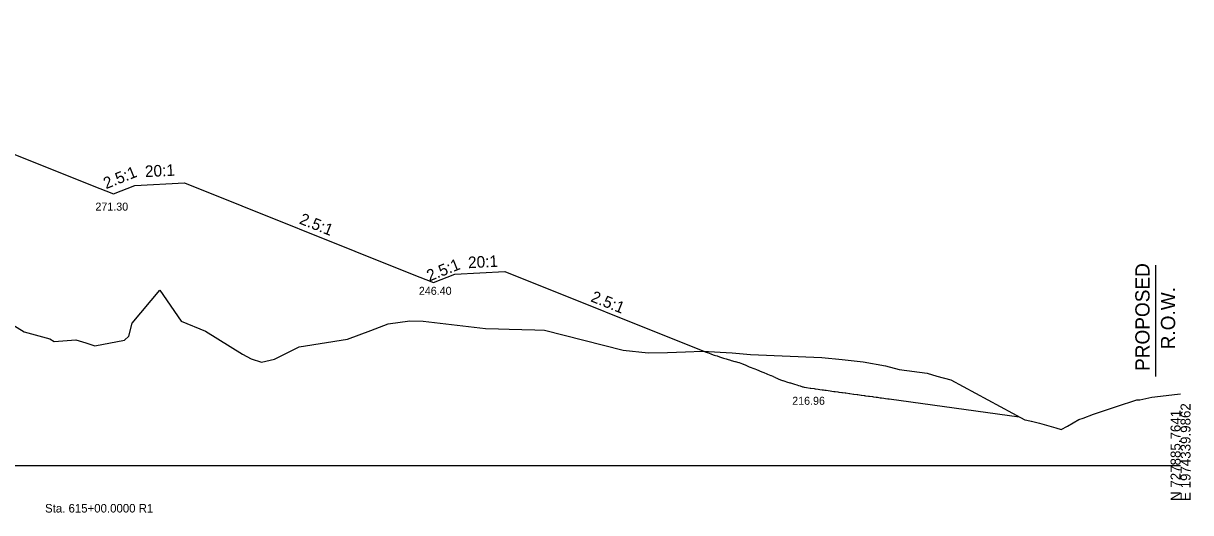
# Model space of a CAD drawing. Extents: x -26 to 1604, y -13 to 9623.
# Drawn here: x 274.6 to 602.8, y 7486.7 to 7624.3 of the extents above; entities that cross this region are included whole.
import ezdxf

# ---------------------------------------------------------------- set-up
doc = ezdxf.new("R2010")
doc.units = 0
for name, color, linetype in [('Default', 7, 'Continuous'), ('Draft_XS_Text', 7, 'Continuous'), ('DTM CONTOURS_MAJOR', 7, 'Continuous'), ('DTM_X_GROUND', 7, 'Continuous'), ('SLOPE_STAKES_FILL', 7, 'Continuous'), ('XS_CELL', 7, 'Continuous'), ('XS_P_GROUND', 7, 'Continuous'), ('XS_P_ROW', 7, 'Continuous'), ('XS_P_TX_DCH', 7, 'Continuous'), ('XS_P_TX_FS_BS', 7, 'Continuous')]:
    doc.layers.add(name, color=color, linetype=linetype)

msp = doc.modelspace()

# ---------------------------------------------------------------- linework, layer by layer
at = {"layer": 'DTM_X_GROUND'}
msp.add_lwpolyline([(269.72, 7540.77), (274.89, 7537.54), (282.09, 7535.56), (283.29, 7534.81), (289.43, 7535.33), (292.18, 7534.46), (294.73, 7533.65), (303.1, 7535.17), (304.3, 7536.31), (305.2, 7539.95), (313.03, 7549.27), (319.02, 7540.54), (325.89, 7537.71), (336.27, 7531.28), (338.67, 7529.99), (341.63, 7528.98), (345.22, 7529.84), (352.21, 7533.32), (365.74, 7535.45), (372.32, 7537.95), (377.24, 7539.82), (383.32, 7540.6), (387.02, 7540.5), (404.55, 7538.51), (408.22, 7538.4), (411.21, 7538.31), (414.82, 7538.19), (418.44, 7538.07), (421.16, 7537.97), (443.29, 7532.39), (450.3, 7531.61), (455.71, 7531.78), (460.79, 7531.93), (465.59, 7532.08), (473.92, 7531.67), (479.05, 7531.13), (499.11, 7530.37), (504.84, 7529.73), (510.79, 7529.07), (517.05, 7527.95), (520.87, 7526.94), (528.77, 7525.91), (531.52, 7525.13), (535.37, 7524.03), (556.23, 7512.79), (556.81, 7512.73), (557.98, 7512.44), (558.05, 7512.43), (560.36, 7511.86), (564.93, 7510.52), (566.47, 7510.07), (568.19, 7511.05), (571.37, 7512.86), (572.65, 7513.3), (575.49, 7514.38), (581.99, 7516.57), (587.71, 7518.39), (588.59, 7518.47), (591.9, 7519.15), (599.1, 7519.98), (600, 7520.14)], dxfattribs=at)
at = {"layer": 'XS_CELL'}
msp.add_line((100, 7500), (600, 7500), dxfattribs=at)
at = {"layer": 'XS_P_GROUND'}
for points in [[(142, 7624.27), (204, 7603.6), (210, 7601.6), (216, 7603.6), (230, 7604.3), (294, 7578.7), (300, 7576.3), (306, 7578.7), (320, 7579.4), (384, 7553.8), (390, 7551.4), (396, 7553.8), (410, 7554.5), (466.14, 7532.04)], [(466.14, 7532.04), (466.36, 7531.96), (466.37, 7531.95), (466.95, 7531.72), (467.02, 7531.7), (467.89, 7531.36), (468.13, 7531.29), (468.88, 7531), (469.24, 7530.89), (469.69, 7530.76), (470.35, 7530.52), (470.95, 7530.35), (471.46, 7530.16), (472.2, 7529.96), (472.57, 7529.83), (473.44, 7529.59), (473.68, 7529.51), (474.68, 7529.24), (474.79, 7529.2), (475.84, 7528.93), (475.89, 7528.91), (475.91, 7528.9), (476.82, 7528.53), (477.02, 7528.45), (477.08, 7528.43), (477.1, 7528.42), (477.8, 7528.14), (478.13, 7528), (478.75, 7527.75), (479.24, 7527.55), (479.76, 7527.34), (480.35, 7527.1), (480.77, 7526.93), (481.46, 7526.65), (481.8, 7526.51), (482.57, 7526.19), (482.84, 7526.08), (483.68, 7525.74), (483.89, 7525.66), (484.79, 7525.29), (484.88, 7525.26), (485.4, 7525.04), (485.45, 7525.02), (485.9, 7524.8), (486, 7524.75), (486.5, 7524.51), (487.01, 7524.26), (487.04, 7524.25), (487.32, 7524.11)], [(487.32, 7524.11), (487.5, 7524.05), (488.12, 7523.86), (488.19, 7523.84), (488.48, 7523.75), (488.75, 7523.66), (488.76, 7523.66), (489.21, 7523.52), (489.24, 7523.51), (490.19, 7523.21), (490.35, 7523.17), (491.18, 7522.91), (491.46, 7522.82), (492.14, 7522.61), (492.57, 7522.47), (493.04, 7522.33), (493.68, 7522.13), (493.86, 7522.07), (494.21, 7521.96), (494.79, 7521.88), (494.85, 7521.87), (495.9, 7521.73), (496.08, 7521.71), (497.01, 7521.58), (497.31, 7521.54), (498.12, 7521.42), (498.54, 7521.37), (499.23, 7521.27), (499.44, 7521.24), (499.59, 7521.22), (500, 7521.17), (500.34, 7521.12), (500.89, 7521.04), (501.45, 7520.97), (501.91, 7520.9), (502.56, 7520.81), (502.93, 7520.76), (503.68, 7520.66), (503.93, 7520.63), (504.79, 7520.51), (504.91, 7520.49), (505.7, 7520.38), (505.89, 7520.36), (505.9, 7520.36), (506.95, 7520.21), (507.01, 7520.2), (508.02, 7520.06), (508.12, 7520.05), (509.09, 7519.92), (509.23, 7519.9), (510.16, 7519.77), (510.34, 7519.75), (511.01, 7519.65), (511.16, 7519.63), (511.39, 7519.6), (511.45, 7519.59), (512.31, 7519.48), (512.56, 7519.44), (513.39, 7519.33), (513.67, 7519.29), (514.46, 7519.18), (514.78, 7519.14), (515.54, 7519.03), (515.89, 7518.98), (516.62, 7518.88), (517, 7518.83), (517.7, 7518.73), (518.12, 7518.68), (554.61, 7513.66)]]:
    msp.add_lwpolyline(points, dxfattribs=at)
at = {"layer": 'XS_P_ROW'}
msp.add_line((593, 7556.27), (593, 7525), dxfattribs=at)

# ---------------------------------------------------------------- texts
at = {"layer": 'Default'}
msp.add_text('X', height=0.12, dxfattribs=at).set_placement((494.18, 7521.9))
at = {"layer": 'Draft_XS_Text'}
msp.add_text('Sta. 615+00.0000 R1', height=2.4, dxfattribs=at).set_placement((280.75, 7486.75))
at = {"layer": 'DTM CONTOURS_MAJOR'}
for p in [(475.8, 7528.87), (487.28, 7524.05), (487.28, 7524.05), (505.66, 7520.32)]:
    msp.add_text('X', height=0.12, dxfattribs=at).set_placement(p)
at = {"layer": 'SLOPE_STAKES_FILL'}
for p in [(293.96, 7578.64), (305.96, 7578.64), (319.96, 7579.34), (299.96, 7576.24), (383.96, 7553.74), (395.96, 7553.74), (409.96, 7554.44), (389.96, 7551.34)]:
    msp.add_text('X', height=0.12, dxfattribs=at).set_placement(p)
at = {"layer": 'XS_CELL'}
for s, p in [('E 1974339.9862', (602.8, 7490)), ('N 727885.7641', (600, 7490))]:
    msp.add_text(s, height=2.8, rotation=90, dxfattribs=at).set_placement(p)
at = {"layer": 'XS_P_GROUND'}
msp.add_text('X', height=0.12, dxfattribs=at).set_placement((466.1, 7531.98))
at = {"layer": 'XS_P_ROW'}
for s, p in [('PROPOSED', (591.28, 7526.54)), ('R.O.W.', (598.48, 7532.62))]:
    msp.add_text(s, height=4, rotation=90, dxfattribs=at).set_placement(p)
at = {"layer": 'XS_P_TX_DCH'}
for s, p in [('271.30', (294.91, 7571.62)), ('246.40', (385.85, 7547.95)), ('216.96', (490.81, 7517.04))]:
    msp.add_text(s, height=2.25, dxfattribs=at).set_placement(p)
at = {"layer": 'XS_P_TX_FS_BS'}
for s, rotation, p in [('20:1', 2.8624, (308.91, 7581.03)), ('2.5:1', 21.8014, (297.91, 7577.64)), ('2.5:1', 338.1986, (352, 7568.05)), ('20:1', 2.8624, (399.75, 7555.42)), ('2.5:1', 21.8014, (388.8, 7551.67)), ('2.5:1', 338.1986, (433.94, 7546.19))]:
    msp.add_text(s, height=3.24, rotation=rotation, dxfattribs=at).set_placement(p)

doc.saveas('drawing.dxf')
